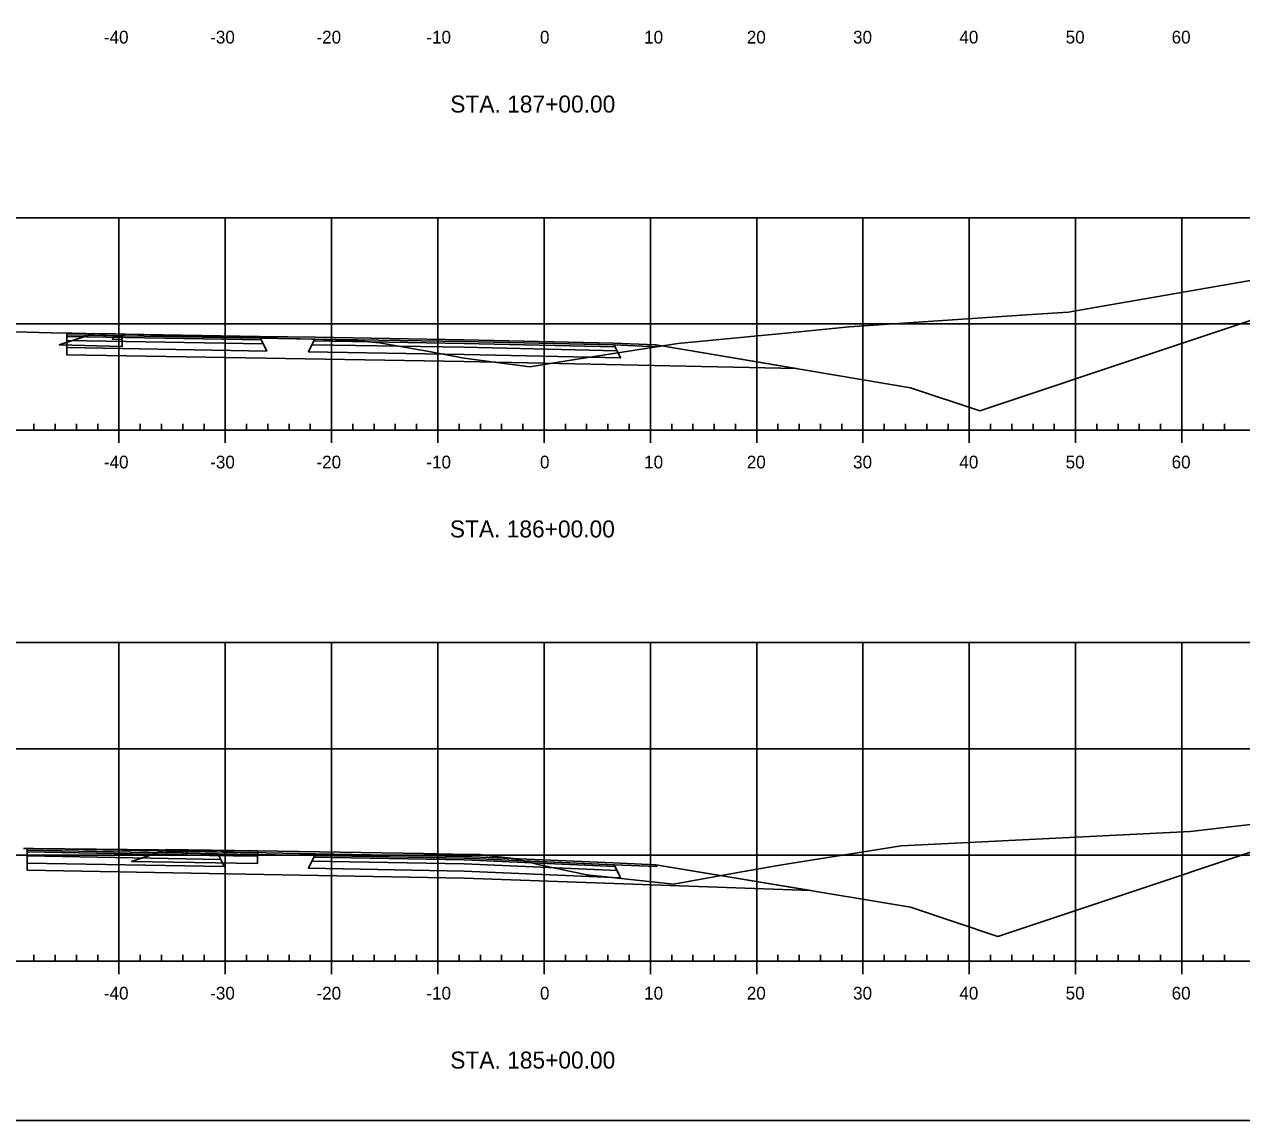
# Model space of a CAD drawing. Extents: x 659657 to 668193, y 633084 to 648639.
# Drawn here: x 667613.6 to 667728.1, y 643502.4 to 643605.6 of the extents above; entities that cross this region are included whole.
import ezdxf

# ---------------------------------------------------------------- set-up
doc = ezdxf.new("R2010")
doc.units = 0
for name, color, linetype in [('Default', 7, 'Continuous'), ('R_Axis', 7, 'Continuous'), ('R_Axis Annot', 7, 'Continuous'), ('R_Exist Surface', 7, 'Continuous'), ('R_Fin Surface', 7, 'Continuous'), ('R_Grid', 7, 'Continuous'), ('R_Sub Surface', 7, 'Continuous'), ('T_SIGNAL CONTROL CABINET', 7, 'Continuous'), ('TEMP_SIGNAL_HEAD_STAGE 5', 7, 'Continuous')]:
    doc.layers.add(name, color=color, linetype=linetype)

msp = doc.modelspace()

# ---------------------------------------------------------------- linework, layer by layer
for points in [[(667617.6, 643576.53), (667635.73, 643576.22), (667641.01, 643576.13), (667655, 643575.89), (667669.01, 643575.58), (667673.01, 643575.41), (667673.09, 643575.24), (667669.1, 643575.41), (667655, 643575.73), (667640.93, 643575.97), (667635.81, 643576.06), (667617.6, 643576.37)], [(667622.82, 643576.43), (667622.14, 643576.45), (667620.14, 643576.49), (667620.06, 643576.33), (667622.06, 643576.28), (667622.82, 643576.26)], [(667613.86, 643528.01), (667631.73, 643527.69), (667641.01, 643527.52), (667655, 643527.26), (667669.01, 643526.65), (667673.01, 643526.48), (667673.09, 643526.31), (667669.1, 643526.48), (667655, 643527.09), (667640.93, 643527.35), (667631.81, 643527.52), (667613.86, 643527.85)], [(667635.53, 643527.78), (667629.03, 643527.88), (667627.03, 643527.91), (667626.95, 643527.74), (667628.95, 643527.71), (667635.53, 643527.61)]]:
    msp.add_lwpolyline(points, close=True)
at = {"layer": 'Default'}
for points in [[(667616.89, 643575.41), (667619, 643576.11), (667620.1, 643576.48), (667620.13, 643576.49), (667620.14, 643576.49), (667621.56, 643576.46), (667622.14, 643576.45), (667622.69, 643576.43), (667622.82, 643576.43), (667622.82, 643576.43), (667622.82, 643576.43)], [(667623.7, 643526.79), (667625.7, 643527.46), (667626.91, 643527.87), (667626.98, 643527.89), (667627.03, 643527.91), (667628.42, 643527.89), (667629.03, 643527.88), (667634.75, 643527.79), (667635.53, 643527.78), (667635.53, 643527.78), (667635.53, 643527.78)]]:
    msp.add_lwpolyline(points, dxfattribs=at)
at = {"layer": 'R_Axis'}
for p, q in [((667622.51, 643566.19), (667622.51, 643568.59)), ((667632.51, 643566.19), (667632.51, 643568.59)), ((667642.51, 643566.19), (667642.51, 643568.59)), ((667652.51, 643566.19), (667652.51, 643568.59)), ((667662.51, 643566.19), (667662.51, 643568.59)), ((667672.51, 643566.19), (667672.51, 643568.59)), ((667682.51, 643566.19), (667682.51, 643568.59)), ((667692.51, 643566.19), (667692.51, 643568.59)), ((667702.51, 643566.19), (667702.51, 643568.59)), ((667712.51, 643566.19), (667712.51, 643568.59)), ((667722.51, 643566.19), (667722.51, 643568.59)), ((667512.51, 643567.39), (667812.51, 643567.39)), ((667614.51, 643567.39), (667614.51, 643567.99)), ((667616.51, 643567.39), (667616.51, 643567.99)), ((667618.51, 643567.39), (667618.51, 643567.99)), ((667620.51, 643567.39), (667620.51, 643567.99)), ((667624.51, 643567.39), (667624.51, 643567.99)), ((667626.51, 643567.39), (667626.51, 643567.99)), ((667628.51, 643567.39), (667628.51, 643567.99)), ((667630.51, 643567.39), (667630.51, 643567.99)), ((667634.51, 643567.39), (667634.51, 643567.99)), ((667636.51, 643567.39), (667636.51, 643567.99)), ((667638.51, 643567.39), (667638.51, 643567.99)), ((667640.51, 643567.39), (667640.51, 643567.99)), ((667644.51, 643567.39), (667644.51, 643567.99)), ((667646.51, 643567.39), (667646.51, 643567.99)), ((667648.51, 643567.39), (667648.51, 643567.99)), ((667650.51, 643567.39), (667650.51, 643567.99)), ((667654.51, 643567.39), (667654.51, 643567.99)), ((667656.51, 643567.39), (667656.51, 643567.99)), ((667658.51, 643567.39), (667658.51, 643567.99)), ((667660.51, 643567.39), (667660.51, 643567.99)), ((667664.51, 643567.39), (667664.51, 643567.99)), ((667666.51, 643567.39), (667666.51, 643567.99)), ((667668.51, 643567.39), (667668.51, 643567.99)), ((667670.51, 643567.39), (667670.51, 643567.99)), ((667674.51, 643567.39), (667674.51, 643567.99)), ((667676.51, 643567.39), (667676.51, 643567.99)), ((667678.51, 643567.39), (667678.51, 643567.99)), ((667680.51, 643567.39), (667680.51, 643567.99)), ((667684.51, 643567.39), (667684.51, 643567.99)), ((667686.51, 643567.39), (667686.51, 643567.99)), ((667688.51, 643567.39), (667688.51, 643567.99)), ((667690.51, 643567.39), (667690.51, 643567.99)), ((667694.51, 643567.39), (667694.51, 643567.99)), ((667696.51, 643567.39), (667696.51, 643567.99)), ((667698.51, 643567.39), (667698.51, 643567.99)), ((667700.51, 643567.39), (667700.51, 643567.99)), ((667704.51, 643567.39), (667704.51, 643567.99)), ((667706.51, 643567.39), (667706.51, 643567.99)), ((667708.51, 643567.39), (667708.51, 643567.99)), ((667710.51, 643567.39), (667710.51, 643567.99)), ((667714.51, 643567.39), (667714.51, 643567.99)), ((667716.51, 643567.39), (667716.51, 643567.99)), ((667718.51, 643567.39), (667718.51, 643567.99)), ((667720.51, 643567.39), (667720.51, 643567.99)), ((667724.51, 643567.39), (667724.51, 643567.99)), ((667726.51, 643567.39), (667726.51, 643567.99)), ((667614.51, 643517.39), (667614.51, 643517.99)), ((667616.51, 643517.39), (667616.51, 643517.99)), ((667618.51, 643517.39), (667618.51, 643517.99)), ((667620.51, 643517.39), (667620.51, 643517.99)), ((667622.51, 643516.19), (667622.51, 643518.59)), ((667624.51, 643517.39), (667624.51, 643517.99)), ((667626.51, 643517.39), (667626.51, 643517.99)), ((667628.51, 643517.39), (667628.51, 643517.99)), ((667630.51, 643517.39), (667630.51, 643517.99)), ((667632.51, 643516.19), (667632.51, 643518.59)), ((667634.51, 643517.39), (667634.51, 643517.99)), ((667636.51, 643517.39), (667636.51, 643517.99)), ((667638.51, 643517.39), (667638.51, 643517.99)), ((667640.51, 643517.39), (667640.51, 643517.99)), ((667642.51, 643516.19), (667642.51, 643518.59)), ((667644.51, 643517.39), (667644.51, 643517.99)), ((667646.51, 643517.39), (667646.51, 643517.99)), ((667648.51, 643517.39), (667648.51, 643517.99)), ((667650.51, 643517.39), (667650.51, 643517.99)), ((667652.51, 643516.19), (667652.51, 643518.59)), ((667654.51, 643517.39), (667654.51, 643517.99)), ((667656.51, 643517.39), (667656.51, 643517.99)), ((667658.51, 643517.39), (667658.51, 643517.99)), ((667660.51, 643517.39), (667660.51, 643517.99)), ((667662.51, 643516.19), (667662.51, 643518.59)), ((667664.51, 643517.39), (667664.51, 643517.99)), ((667666.51, 643517.39), (667666.51, 643517.99)), ((667668.51, 643517.39), (667668.51, 643517.99)), ((667670.51, 643517.39), (667670.51, 643517.99)), ((667672.51, 643516.19), (667672.51, 643518.59)), ((667674.51, 643517.39), (667674.51, 643517.99)), ((667676.51, 643517.39), (667676.51, 643517.99)), ((667678.51, 643517.39), (667678.51, 643517.99)), ((667680.51, 643517.39), (667680.51, 643517.99)), ((667682.51, 643516.19), (667682.51, 643518.59)), ((667684.51, 643517.39), (667684.51, 643517.99)), ((667686.51, 643517.39), (667686.51, 643517.99)), ((667688.51, 643517.39), (667688.51, 643517.99)), ((667690.51, 643517.39), (667690.51, 643517.99)), ((667692.51, 643516.19), (667692.51, 643518.59)), ((667694.51, 643517.39), (667694.51, 643517.99)), ((667696.51, 643517.39), (667696.51, 643517.99)), ((667698.51, 643517.39), (667698.51, 643517.99)), ((667700.51, 643517.39), (667700.51, 643517.99)), ((667702.51, 643516.19), (667702.51, 643518.59)), ((667704.51, 643517.39), (667704.51, 643517.99)), ((667706.51, 643517.39), (667706.51, 643517.99)), ((667708.51, 643517.39), (667708.51, 643517.99)), ((667710.51, 643517.39), (667710.51, 643517.99)), ((667712.51, 643516.19), (667712.51, 643518.59)), ((667714.51, 643517.39), (667714.51, 643517.99)), ((667716.51, 643517.39), (667716.51, 643517.99)), ((667718.51, 643517.39), (667718.51, 643517.99)), ((667720.51, 643517.39), (667720.51, 643517.99)), ((667722.51, 643516.19), (667722.51, 643518.59)), ((667724.51, 643517.39), (667724.51, 643517.99)), ((667726.51, 643517.39), (667726.51, 643517.99)), ((667512.51, 643517.39), (667812.51, 643517.39))]:
    msp.add_line(p, q, dxfattribs=at)
at = {"layer": 'R_Exist Surface'}
for points in [[(667607.97, 643576.69), (667613.86, 643576.6), (667616.12, 643576.56), (667618.1, 643576.52), (667620.69, 643576.47), (667622.82, 643576.43), (667623.13, 643576.42), (667625.52, 643576.38), (667627.62, 643576.31), (667633.04, 643576.16), (667635.44, 643576.1), (667638.39, 643576.02), (667640.64, 643575.96), (667644.04, 643575.87), (667645.31, 643575.77), (667647.01, 643575.61), (667651.5, 643574.82), (667654.99, 643574.17), (667657.8, 643573.79), (667661.16, 643573.35), (667665.63, 643574.08), (667675.09, 643575.54), (667685.24, 643576.51), (667691.2, 643577.13), (667708.38, 643578.27), (667711.86, 643578.51), (667712.89, 643578.7), (667730.94, 643581.84)], [(667613.52, 643528.02), (667614.49, 643528), (667632.09, 643527.81), (667635.53, 643527.78), (667635.55, 643527.78), (667639.4, 643527.72), (667639.4, 643527.72), (667639.42, 643527.72), (667651.16, 643527.55), (667653.89, 643527.49), (667656.01, 643527.45), (667656.49, 643527.44), (667656.72, 643527.4), (667657.33, 643527.33), (667659.66, 643527.06), (667662.08, 643526.47), (667666.54, 643525.52), (667673.82, 643524.73), (667674.68, 643524.64), (667681.46, 643525.86), (667684.34, 643526.38), (667684.89, 643526.47), (667696.1, 643528.26), (667704.98, 643528.71), (667723.29, 643529.61), (667738.44, 643531.37)]]:
    msp.add_lwpolyline(points, dxfattribs=at)
at = {"layer": 'R_Fin Surface'}
for points in [[(667617.6, 643576.37), (667635.81, 643576.06), (667635.9, 643575.89), (667617.6, 643576.2)], [(667617.6, 643576.2), (667635.9, 643575.89), (667636.09, 643575.51), (667617.6, 643575.82)], [(667622.82, 643576.26), (667622.06, 643576.28), (667621.89, 643575.95), (667622.82, 643575.93)], [(667617.6, 643575.82), (667636.09, 643575.51), (667636.42, 643574.84), (667617.6, 643575.16)], [(667640.66, 643575.43), (667655, 643575.19), (667669.37, 643574.86), (667669.71, 643574.19), (667655, 643574.52), (667640.33, 643574.77)], [(667640.85, 643575.8), (667655, 643575.56), (667669.18, 643575.24), (667669.37, 643574.86), (667655, 643575.19), (667640.66, 643575.43)], [(667669.1, 643575.41), (667655, 643575.73), (667640.93, 643575.97), (667640.85, 643575.8), (667655, 643575.56), (667669.18, 643575.24)], [(667613.86, 643527.85), (667631.81, 643527.52), (667631.89, 643527.35), (667613.86, 643527.68)], [(667613.86, 643527.68), (667631.89, 643527.35), (667632.08, 643526.97), (667613.86, 643527.31)], [(667613.86, 643527.31), (667632.08, 643526.97), (667632.42, 643526.3), (667613.86, 643526.64)], [(667635.53, 643527.61), (667628.95, 643527.71), (667628.78, 643527.38), (667635.53, 643527.28)], [(667640.85, 643527.19), (667655, 643526.93), (667669.18, 643526.32), (667669.37, 643525.93), (667655, 643526.55), (667640.66, 643526.82)], [(667669.1, 643526.48), (667655, 643527.09), (667640.93, 643527.35), (667640.85, 643527.19), (667655, 643526.93), (667669.18, 643526.32)], [(667640.66, 643526.82), (667655, 643526.55), (667669.37, 643525.93), (667669.71, 643525.26), (667655, 643525.88), (667640.33, 643526.16)]]:
    msp.add_lwpolyline(points, close=True, dxfattribs=at)
at = {"layer": 'R_Grid'}
for p, q in [((667512.51, 643587.39), (667812.51, 643587.39)), ((667622.51, 643567.39), (667622.51, 643587.39)), ((667632.51, 643567.39), (667632.51, 643587.39)), ((667642.51, 643567.39), (667642.51, 643587.39)), ((667652.51, 643567.39), (667652.51, 643587.39)), ((667662.51, 643567.39), (667662.51, 643587.39)), ((667672.51, 643567.39), (667672.51, 643587.39)), ((667682.51, 643567.39), (667682.51, 643587.39)), ((667692.51, 643567.39), (667692.51, 643587.39)), ((667702.51, 643567.39), (667702.51, 643587.39)), ((667712.51, 643567.39), (667712.51, 643587.39)), ((667722.51, 643567.39), (667722.51, 643587.39)), ((667512.51, 643577.39), (667812.51, 643577.39)), ((667512.51, 643567.39), (667812.51, 643567.39)), ((667512.51, 643547.39), (667812.51, 643547.39)), ((667622.51, 643517.39), (667622.51, 643547.39)), ((667632.51, 643517.39), (667632.51, 643547.39)), ((667642.51, 643517.39), (667642.51, 643547.39)), ((667652.51, 643517.39), (667652.51, 643547.39)), ((667662.51, 643517.39), (667662.51, 643547.39)), ((667672.51, 643517.39), (667672.51, 643547.39)), ((667682.51, 643517.39), (667682.51, 643547.39)), ((667692.51, 643517.39), (667692.51, 643547.39)), ((667702.51, 643517.39), (667702.51, 643547.39)), ((667712.51, 643517.39), (667712.51, 643547.39)), ((667722.51, 643517.39), (667722.51, 643547.39)), ((667512.51, 643537.39), (667812.51, 643537.39)), ((667512.51, 643527.39), (667812.51, 643527.39)), ((667512.51, 643517.39), (667812.51, 643517.39))]:
    msp.add_line(p, q, dxfattribs=at)
at = {"layer": 'R_Sub Surface'}
for points in [[(667622.82, 643575.93), (667621.89, 643575.95), (667622.06, 643576.28), (667622.82, 643576.26), (667622.06, 643576.28), (667620.06, 643576.33), (667620.14, 643576.49), (667616.89, 643575.41), (667622.82, 643575.26)], [(667617.6, 643575.16), (667636.42, 643574.84), (667635.81, 643576.06), (667640.93, 643575.97), (667640.33, 643574.77), (667655, 643574.52), (667669.71, 643574.19), (667669.1, 643575.41), (667673.09, 643575.24), (667673.01, 643575.41), (667686.27, 643573.19), (667655, 643573.85), (667617.6, 643574.49)], [(667613.86, 643526.64), (667632.42, 643526.3), (667631.81, 643527.52), (667640.93, 643527.35), (667640.33, 643526.16), (667655, 643525.88), (667669.71, 643525.26), (667669.1, 643526.48), (667673.09, 643526.31), (667673.01, 643526.48), (667687.59, 643524.05), (667655, 643525.22), (667613.86, 643525.97)], [(667635.53, 643527.28), (667628.78, 643527.38), (667628.95, 643527.71), (667635.53, 643527.61), (667628.95, 643527.71), (667626.95, 643527.74), (667627.03, 643527.91), (667623.7, 643526.79), (667635.53, 643526.61)]]:
    msp.add_lwpolyline(points, close=True, dxfattribs=at)
at = {"layer": 'T_SIGNAL CONTROL CABINET'}
msp.add_lwpolyline([(667502.51, 643502.39), (667842.51, 643502.39), (667842.51, 643722.39), (667502.51, 643722.39)], close=True, dxfattribs=at)
at = {"layer": 'TEMP_SIGNAL_HEAD_STAGE 5'}
for points in [[(667673.01, 643575.41), (667696.99, 643571.39), (667703.5, 643569.21), (667737.3, 643580.51)], [(667620.14, 643576.49), (667620.1, 643576.48)], [(667673.01, 643526.48), (667696.99, 643522.48), (667705.21, 643519.73), (667741.31, 643531.77)], [(667627.03, 643527.91), (667626.91, 643527.87)]]:
    msp.add_lwpolyline(points, dxfattribs=at)

# ---------------------------------------------------------------- texts
at = {"layer": 'R_Axis Annot'}
for s, height, p in [('-40', 1.2, (667621.09, 643603.79)), ('-30', 1.2, (667631.09, 643603.79)), ('-20', 1.2, (667641.09, 643603.79)), ('-10', 1.2, (667651.43, 643603.79)), ('0', 1.2, (667662.12, 643603.79)), ('10', 1.2, (667671.92, 643603.79)), ('20', 1.2, (667681.58, 643603.79)), ('30', 1.2, (667691.58, 643603.79)), ('40', 1.2, (667701.58, 643603.79)), ('50', 1.2, (667711.58, 643603.79)), ('60', 1.2, (667721.55, 643603.79)), ('STA. 187+00.00', 1.6, (667653.68, 643597.29)), ('-40', 1.2, (667621.09, 643563.79)), ('-30', 1.2, (667631.09, 643563.79)), ('-20', 1.2, (667641.09, 643563.79)), ('-10', 1.2, (667651.43, 643563.79)), ('0', 1.2, (667662.12, 643563.79)), ('10', 1.2, (667671.92, 643563.79)), ('20', 1.2, (667681.58, 643563.79)), ('30', 1.2, (667691.58, 643563.79)), ('40', 1.2, (667701.58, 643563.79)), ('50', 1.2, (667711.58, 643563.79)), ('60', 1.2, (667721.55, 643563.79)), ('STA. 186+00.00', 1.6, (667653.64, 643557.29)), ('-40', 1.2, (667621.09, 643513.79)), ('-30', 1.2, (667631.09, 643513.79)), ('-20', 1.2, (667641.09, 643513.79)), ('-10', 1.2, (667651.43, 643513.79)), ('0', 1.2, (667662.12, 643513.79)), ('10', 1.2, (667671.92, 643513.79)), ('20', 1.2, (667681.58, 643513.79)), ('30', 1.2, (667691.58, 643513.79)), ('40', 1.2, (667701.58, 643513.79)), ('50', 1.2, (667711.58, 643513.79)), ('60', 1.2, (667721.55, 643513.79)), ('STA. 185+00.00', 1.6, (667653.68, 643507.29))]:
    msp.add_text(s, height=height, dxfattribs=at).set_placement(p)

doc.saveas('drawing.dxf')
